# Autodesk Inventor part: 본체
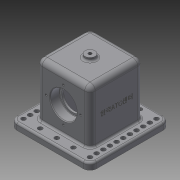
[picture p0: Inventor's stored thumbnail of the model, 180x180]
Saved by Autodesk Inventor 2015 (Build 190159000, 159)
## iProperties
Created: 2018-11
Part Number: 본체
Material: 일반
Document SubType Name: Modeling
Designer: now
Density: 1 g/cm^3
Appearance: 기본값
Mass: 376.063 g
Surface Area: 780.986 cm^2
Volume: 376.063 cm^3
Author: now
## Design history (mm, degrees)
sketch "스케치1"
  geometry: L1 (-60, 60)-(60, 60); L2 (60, 60)-(60, -60); L3 (60, -60)-(-60, -60); L4 (-60, -60)-(-60, 60); L5 (-60, 60)-(60, -60); L6 (60, 60)-(-60, -60); 1 further point
  constraints: 12 end point, 2 midpoint, 2 parallel, 1 horizontal, 1 perpendicular
  dimensions: "d0" = 120 distance of L3.end L1.start; "d1" = 120 distance of L1.start L1.end
extrude "돌출1" new body sketch "스케치1" distance "d2" = 10; taper "d3" = 0 deg
sketch "스케치2"
  geometry: L1 (-40, 40)-(40, 40); L2 (40, 40)-(40, -40); L3 (40, -40)-(-40, -40); L4 (-40, -40)-(-40, 40); L5 (-40, 40)-(40, -40); L6 (40, 40)-(-40, -40); 1 further point
  constraints: 12 end point, 2 midpoint, 2 parallel, 1 horizontal, 1 perpendicular
  dimensions: "d4" = 80 distance of L2.end L3.end; "d5" = 80 distance of L1.end L2.end
extrude "돌출2" join sketch "스케치2" distance "d6" = 80; taper "d7" = 0 deg
sketch "스케치3"
  geometry: L1 (30, 23)-(-30, 23); L2 (-30, 23)-(-30, -23); L3 (-30, -23)-(30, -23); L4 (30, -23)-(30, 23); L5 (30, 23)-(-30, -23); L6 (-30, 23)-(30, -23); 1 further point
  constraints: 12 end point, 2 midpoint, 2 parallel, 1 horizontal, 1 perpendicular
  dimensions: "d8" = 60 distance of L2.end L3.end; "d9" = 46 distance of L1.end L2.end
extrude "돌출3" cut sketch "스케치3" distance "d10" = 80; taper "d11" = 0 deg
sketch "스케치4"
  geometry: L1 (-20, -10)-(-20, 0) reference; L2 (-20, 0)-(0, 0) reference; L3 (0, 0)-(0, 80) reference; L4 (0, 80)-(80, 80) reference; L5 (80, 80)-(80, 0) reference; L6 (80, 0)-(100, 0) reference; L7 (100, 0)-(100, -10) reference; L8 (100, -10)-(-20, -10) reference; L9 (0, 0)-(80, 0) reference; C1 r 16.5 at (40, 38); 2 further points
  constraints: 1 centre point, 1 midpoint, 1 vertical alignment
  dimensions: "d12" = 33 diameter of C1; "d13" = 48 distance of point (40, -10) C1.centre
extrude "돌출4" cut sketch "스케치4" stored distance "d14" = 80; taper "d15" = 0 deg
sketch "스케치5"
  geometry: C1 r 16.5 at (40, 38) reference; C2 r 20 at (40, 38); 1 further point
  constraints: 1 centre point, 1 coincident
  dimensions: "d16" = 40 diameter of C2
extrude "돌출5" cut sketch "스케치5" distance "d17" = 14; taper "d18" = 0 deg
fillet "모깎기1" dims "d19" = 0.6
node "작업 평면1"
sketch "스케치6"
  geometry: C1 r 7.5 at (0, 0); 1 further point
  constraints: 1 centre point, 1 coincident
  dimensions: "d21" = 15 diameter of C1
extrude "돌출6" join sketch "스케치6" stored distance "d22" = 14; taper "d23" = 0 deg
sketch "스케치7"
  geometry: C1 r 7.5 at (0, 0) reference
hole "구멍1" sketch "스케치7" at (0, 0) diameter "d24" = 4.917; stored, may be unused: countersink angle "d28" = 90 deg, drill point angle "d30" = 0 deg; dims "d25" = 15, "d26" = 4, "d27" = 2, "d29" = 16
sketch "스케치8" dims "d31" = 52
  geometry: C1 r 20 at (40, 38) reference; 3 further points
  constraints: 2 vertical alignment, 1 coincident, 2 other
hole "구멍2" sketch "스케치8" at (40, 64) diameter "d32" = 3.242; stored, may be unused: countersink angle "d36" = 90 deg, drill point angle "d38" = 118 deg; dims "d33" = 8, "d34" = 4, "d35" = 2, "d37" = 10
fillet "모깎기2" dims "d42" = 10
sketch "스케치9"
  geometry: L1 (-60, -50)-(-60, 50) reference; L2 (-50, 60)-(50, 60) reference; L3 (60, 50)-(60, -50) reference; L4 (50, -60)-(-50, -60) reference; L5 (30, -23)-(30, 23) reference; L6 (30, 23)-(-30, 23) reference; L7 (-30, 23)-(-30, -23) reference; L8 (-30, -23)-(30, -23) reference; L9 (40, 40)-(40, -40) reference; L10 (40, -40)-(-40, -40) reference; L11 (-40, -40)-(-40, 40) reference; L12 (-40, 40)-(40, 40) reference; A1 r 10 centre (-50, -50) between (-60, -50) and (-50, -60) reference; A2 r 10 centre (-50, -50) between (-60, -50) and (-50, -60) reference; A3 r 10 centre (-50, 50) between (-50, 60) and (-60, 50) reference; A4 r 10 centre (50, 50) between (60, 50) and (50, 60) reference; A5 r 10 centre (50, -50) between (50, -60) and (60, -50) reference; 1 further point
hole "구멍3" sketch "스케치9" at (-50, -50) diameter "d43" = 6.6; stored, may be unused: countersink angle "d47" = 90 deg, drill point angle "d49" = 118 deg; dims "d44" = 8, "d45" = 4, "d46" = 2, "d48" = 10
fillet "모깎기3" dims "d62" = 8
fillet "모깎기4" dims "d63" = 8
fillet "모깎기5" dims "d64" = 3
fillet "모깎기6" dims "d65" = 3
chamfer "모따기1" distance "d66" = 1; stored, may be unused: second distance "d67" = 2, angle "d68" = 45 deg
chamfer "모따기2" distance "d69" = 1; stored, may be unused: second distance "d70" = 2, angle "d71" = 45 deg
sketch "스케치10"
  geometry: L1 (10, 82)-(10, -18) reference; L2 (-72, -8)-(0, -8) reference; 2 further points
  constraints: 1 other
  dimensions: "d72" = 48 distance from line of L1 point (-38, 32); "d73" = 40 distance from line of L2 point (-38, 32)
feature "엠보싱1" sketch "스케치10" dims "d0" = 120, "d1" = 120, "d8" = 60, "d9" = 46, "d74" = 0.5, "d75" = 0
fillet "모깎기7" dims "d76" = 3
node "솔리드1"
mirror "대칭1"
pattern_circular "원형 패턴1" dims angle "d40" = 360 deg
mirror "대칭2"
pattern_linear "직사각형 패턴1" dims "d52" = 10
pattern_linear "직사각형 패턴2" dims "d58" = 25
node "절단 모서리 투영1"
node "절단 모서리 투영2"
other parameters: "d20" = 95
